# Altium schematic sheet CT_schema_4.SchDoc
size 300 x 247 mm
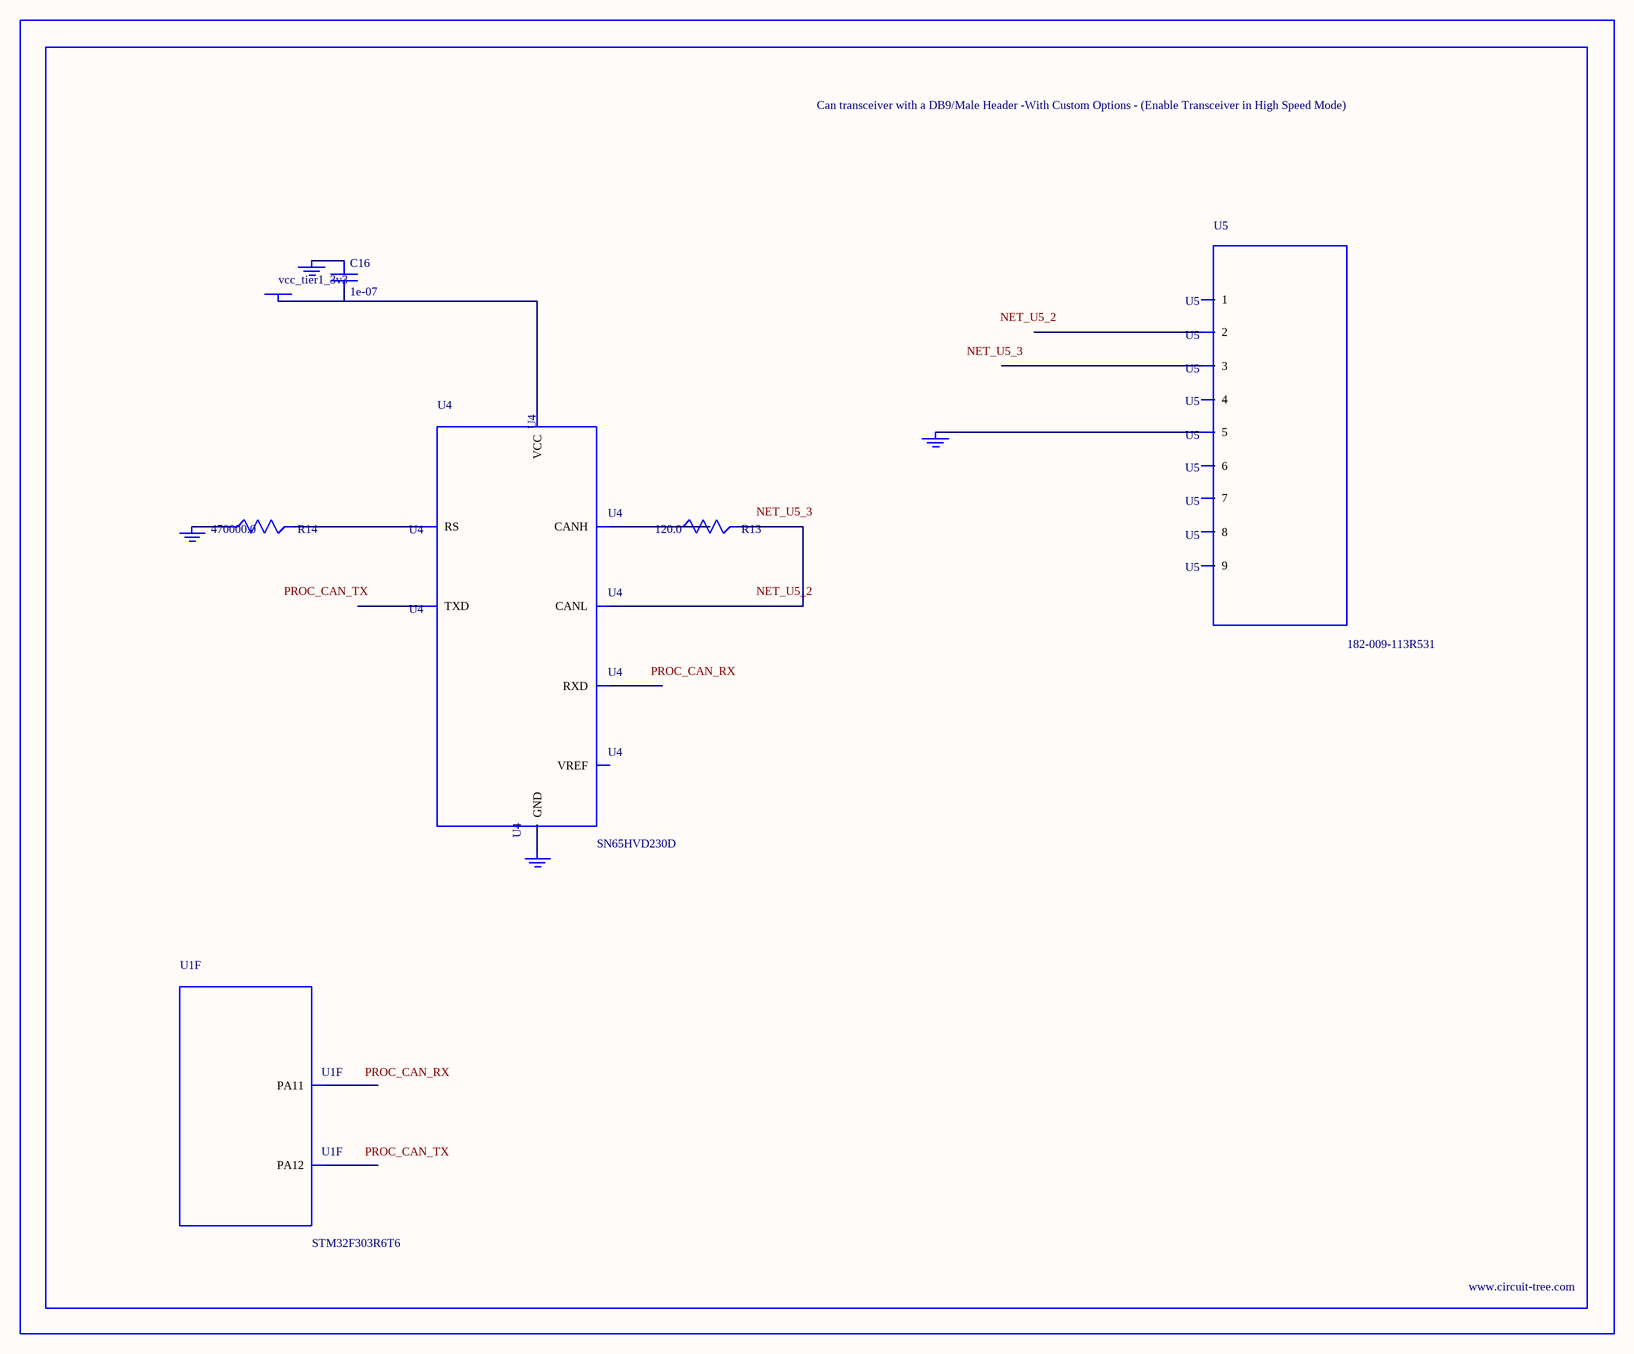
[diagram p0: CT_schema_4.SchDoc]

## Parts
BORDER3  (no value)
C16  1e-07  [C0402]
GND_INSTANCE_3_0  (no value)
GND_INSTANCE_3_1  (no value)
GND_INSTANCE_3_2  (no value)
GND_INSTANCE_3_3  (no value)
POWER_INSTANCE_3_0  vcc_tier1_3v3
R13  120.0  [R0603]
R14  470000.0  [R0603]
U1  STM32F303R6T6  [LQFP64]  (part F of 7)
U4  SN65HVD230D  [SOIC-8]
U5  182-009-113R531  [182-009-MALE]

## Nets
NetC16_1: C16.1 GND_INSTANCE_3_0.0(GND)
NetC16_2: C16.2 POWER_INSTANCE_3_0.0(PWR) U4.3(VCC)
NetGND_INSTANCE_3_1_0: GND_INSTANCE_3_1.0(GND) R14.1
NetGND_INSTANCE_3_2_0: GND_INSTANCE_3_2.0(GND) U4.2(GND)
NetGND_INSTANCE_3_3_0: GND_INSTANCE_3_3.0(GND) U5.5
NetR13_1: R13.1 U4.7(CANH)
NetR13_2: R13.2 U4.6(CANL)
NetR14_2: R14.2 U4.8(RS)

Not connected (* = marked no-connect by the designer): U1 44(PA11) 45(PA12); U4 1(TXD) 4(RXD) 5(VREF); U5 1 2 3 4 6 7 8 9

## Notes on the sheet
- Labels drawn without touching a wire or pin: NET_U5_2, NET_U5_3, PROC_CAN_RX, PROC_CAN_TX

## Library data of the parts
BORDER3 = BORDER_PAGE3
C16 = C0402C104K3RACTU
GND_INSTANCE_3_0-GND_INSTANCE_3_3 = GND
POWER_INSTANCE_3_0 = PWR
R13 = RC0603JR-07120RL
R14 = RC0603JR-07470KL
